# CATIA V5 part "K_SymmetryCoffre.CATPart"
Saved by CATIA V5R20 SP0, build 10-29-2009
Part number: Symmetry of Coffre
Bounding box of the stored display mesh (mm): x -5 to 330.41, y -5 to 415, z -265 to 0
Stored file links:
  G:\Khaled_CFAO_2011\SIL\SIL_GR2\zthiebault\Khaled\CAD_ThinkMOTION\K_SymmetryCoffre.CATPart
  G:\Khaled_CFAO_2011\SIL\SIL_GR2\zthiebault\Khaled\CAD_ThinkMOTION\K_Paroie_gauche.CATPart
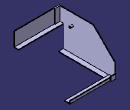
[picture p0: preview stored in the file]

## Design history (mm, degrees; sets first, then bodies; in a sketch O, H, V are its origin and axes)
Body1 (main body)
  Body2 "Corps du corps principal d'origine"
    Solid1: linked copy from another document
  Assemble1: tool Body2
